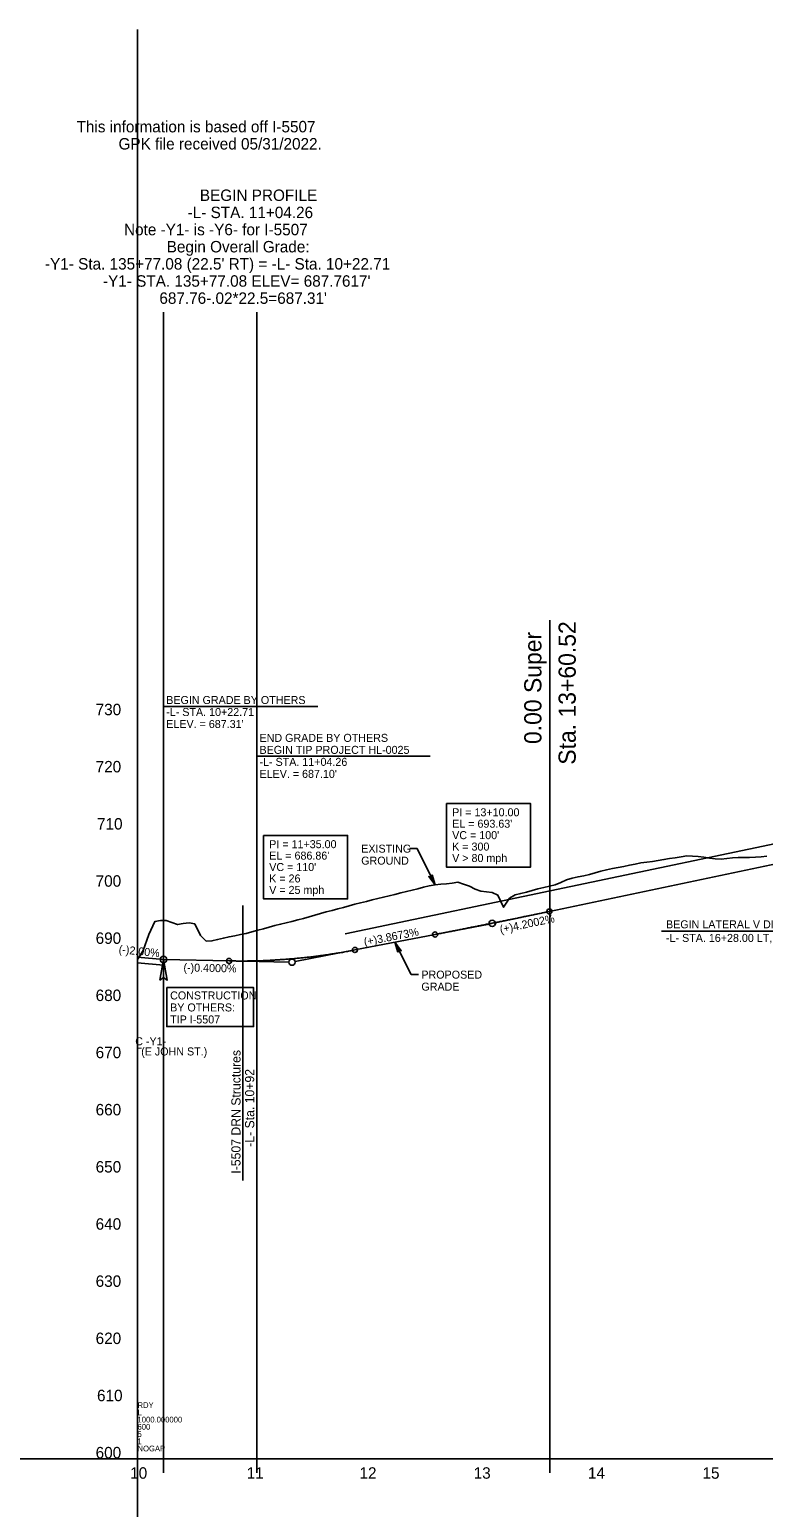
# Model space of a CAD drawing. Extents: x 1518255 to 1527303, y 471773 to 504546.
# Drawn here: x 1519476 to 1520117, y 501102 to 502395 of the extents above; entities that cross this region are included whole.
import ezdxf

# ---------------------------------------------------------------- set-up
doc = ezdxf.new("R2010")
doc.units = 0
for name, color, linetype in [('Default', 7, 'Continuous'), ('Exist Profile Cell', 7, 'Continuous'), ('Exist Vertical Profile Ground Line', 7, 'Continuous'), ('Exist Vertical Profile Horizontal Axis Label Major', 7, 'Continuous'), ('Exist Vertical Profile Vertical Axis Label', 7, 'Continuous'), ('Prop Dimension', 7, 'Continuous'), ('Prop Grid Mask', 7, 'Continuous'), ('Prop PFL Ditch Label CELL', 7, 'Continuous'), ('Prop Shade Light', 7, 'Continuous'), ('Prop Terminator CELL', 7, 'Continuous'), ('Prop Vertical Profile Curve Label', 7, 'Continuous'), ('Prop Vertical Profile Grade', 7, 'Continuous'), ('Prop Vertical Profile Grade Label', 7, 'Continuous'), ('Prop VPI Label', 7, 'Continuous'), ('Scratch_Level_1', 7, 'Continuous'), ('Scratch_Level_5', 7, 'Continuous'), ('Scratch_Level_7', 7, 'Continuous'), ('Scratch_Level_9', 7, 'Continuous')]:
    doc.layers.add(name, color=color, linetype=linetype)

msp = doc.modelspace()

# ---------------------------------------------------------------- linework, layer by layer
at = {"layer": 'Default'}
msp.add_line((1518570.4, 501145), (1519570.4, 501145), dxfattribs=at)
at = {"layer": 'Exist Profile Cell'}
for q in [(1519570.4, 502395), (1521170.4, 501145), (1519570.4, 499895)]:
    msp.add_line((1519570.4, 501145), q, dxfattribs=at)
at = {"layer": 'Exist Vertical Profile Ground Line'}
for points in [[(1519570.4, 501581.5), (1519575.4, 501589.5), (1519580.4, 501603.4), (1519585.4, 501614.8), (1519590.4, 501615.7), (1519595.4, 501615.8), (1519600.4, 501614), (1519605.4, 501612.2), (1519610.4, 501613.2), (1519615.4, 501613.8), (1519620.4, 501612.8), (1519625.4, 501602.5), (1519630.4, 501597.6), (1519635.4, 501597.9), (1519640.4, 501599), (1519645.4, 501600.4), (1519650.4, 501601.5), (1519655.4, 501602.4), (1519660.4, 501603.5), (1519665.4, 501604.5), (1519670.4, 501605.8), (1519675.4, 501607.2), (1519680.4, 501608.6), (1519685.4, 501610), (1519690.4, 501611.3), (1519695.4, 501612.5), (1519700.4, 501613.8), (1519705.4, 501615), (1519710.4, 501616.3), (1519715.4, 501617.6), (1519720.4, 501619), (1519725.4, 501620.5), (1519730.4, 501621.9), (1519735.4, 501623.2), (1519740.4, 501624.5), (1519745.4, 501625.9), (1519750.4, 501627.2), (1519755.4, 501628.6), (1519760.4, 501629.9), (1519765.4, 501631.2), (1519770.4, 501632.5), (1519775.4, 501633.7), (1519780.4, 501634.9), (1519785.4, 501636.2), (1519790.4, 501637.4), (1519795.4, 501638.6), (1519800.4, 501639.9), (1519805.4, 501641.1), (1519810.4, 501642.3), (1519815.4, 501643.5), (1519820.4, 501644.8), (1519825.4, 501646), (1519830.4, 501646.8), (1519835.4, 501647.4), (1519840.4, 501647.9), (1519845.4, 501648.5), (1519850.4, 501649.3), (1519855.4, 501647.5), (1519860.4, 501645.9), (1519865.4, 501643.1), (1519870.4, 501641.3), (1519875.4, 501640.7), (1519880.4, 501640.1), (1519885.4, 501638), (1519890.4, 501627.3), (1519895.4, 501635.2), (1519900.4, 501638.1), (1519905.4, 501639.4), (1519910.4, 501640.6), (1519915.4, 501642), (1519920.4, 501643.3), (1519925.4, 501644.6), (1519930.4, 501645.9), (1519935.4, 501647), (1519940.4, 501649.1), (1519945.4, 501651.4), (1519950.4, 501652.9), (1519955.4, 501654), (1519960.4, 501654.7), (1519965.4, 501656.1), (1519970.4, 501657.4), (1519975.4, 501658.8), (1519980.4, 501660.1), (1519985.4, 501661.1), (1519990.4, 501662.1), (1519995.4, 501663.1), (1520000.4, 501664.1), (1520005.4, 501665.1), (1520010.4, 501666.1), (1520015.4, 501666.7), (1520020.4, 501667.4), (1520025.4, 501668.2), (1520030.4, 501669), (1520035.4, 501669.9), (1520040.4, 501670.7), (1520045.4, 501671.5), (1520050.4, 501672.2), (1520055.4, 501672.1), (1520060.4, 501671.7), (1520065.4, 501671.2), (1520070.4, 501670.4)], [(1520070.4, 501670.4), (1520075.4, 501669.8), (1520080.4, 501669.4), (1520085.4, 501670), (1520090.4, 501670.7), (1520095.4, 501670.9), (1520100.4, 501670.9), (1520105.4, 501670.9), (1520110.4, 501671), (1520115.4, 501671.3), (1520120.4, 501672)]]:
    msp.add_lwpolyline(points, dxfattribs=at)
at = {"layer": 'Prop Dimension'}
for p, q in [((1519808.3, 501678.6), (1519814.7, 501678.6)), ((1519814.7, 501678.6), (1519830.4, 501646.8)), ((1519809.5, 501568.4), (1519795.4, 501596.7)), ((1519815.9, 501568.4), (1519809.5, 501568.4))]:
    msp.add_line(p, q, dxfattribs=at)
at = {"layer": 'Prop Grid Mask'}
for points in [[(1519840.4, 501718), (1519913.9, 501718), (1519913.9, 501662.5), (1519840.4, 501662.5)], [(1519680.5, 501690.2), (1519754, 501690.2), (1519754, 501634.6), (1519680.5, 501634.6)], [(1519595.9, 501557.1), (1519671.9, 501557.1), (1519671.9, 501523), (1519595.9, 501523)]]:
    msp.add_lwpolyline(points, close=True, dxfattribs=at)
at = {"layer": 'Prop PFL Ditch Label CELL'}
msp.add_line((1520028.3, 501606.5), (1520198.4, 501606.5), dxfattribs=at)
at = {"layer": 'Prop Shade Light'}
msp.add_lwpolyline([(1519570.4, 501583.8), (1519593.1, 501581.6), (1519593.1, 501576.6), (1519570.4, 501578.8)], close=True, dxfattribs=at)
at = {"layer": 'Prop Terminator CELL'}
for points in [[(1519827.8, 501655.6), (1519830.4, 501646.8), (1519825, 501654.2), (1519826.9, 501653.9)], [(1519798, 501588), (1519795.4, 501596.7), (1519800.9, 501589.3), (1519798.9, 501589.6)]]:
    msp.add_lwpolyline(points, close=True, dxfattribs=at)
at = {"layer": 'Prop Vertical Profile Curve Label'}
for p, q in [((1519593.1, 501581.6), (1519593.1, 501803)), ((1519593.1, 501803), (1519728.1, 501803)), ((1519674.7, 501580.5), (1519674.7, 501759.4)), ((1519674.7, 501759.4), (1519826.2, 501759.4)), ((1519593.1, 501581.6), (1519570.4, 501583.8)), ((1519570.4, 501583.8), (1519570.4, 501578.8)), ((1519593.1, 501576.6), (1519570.4, 501578.8)), ((1519570.4, 501578.8), (1519570.4, 501516.8)), ((1519593.1, 501576.6), (1519593.1, 501581.6))]:
    msp.add_line(p, q, dxfattribs=at)
for centre in [(1519930.4, 501623.7), (1519830.4, 501603.5), (1519760.4, 501590), (1519650.4, 501580.4)]:
    msp.add_circle(centre, 2.25, dxfattribs=at)
at = {"layer": 'Prop Vertical Profile Grade'}
for p, q in [((1519930.4, 501623.7), (1520335.4, 501708.7)), ((1519760.4, 501590), (1519830.4, 501603.5)), ((1519593.1, 501581.6), (1519650.4, 501580.4))]:
    msp.add_line(p, q, dxfattribs=at)
for points in [[(1519830.4, 501603.5), (1519832.4, 501603.9), (1519834.4, 501604.3), (1519836.4, 501604.7), (1519838.4, 501605), (1519840.4, 501605.4), (1519842.4, 501605.8), (1519844.4, 501606.2), (1519846.4, 501606.6), (1519848.4, 501607), (1519850.4, 501607.4), (1519852.4, 501607.8), (1519854.4, 501608.2), (1519856.4, 501608.6), (1519858.4, 501609), (1519860.4, 501609.4), (1519862.4, 501609.8), (1519864.4, 501610.2), (1519866.4, 501610.6), (1519868.4, 501611), (1519870.4, 501611.4), (1519872.4, 501611.8), (1519874.4, 501612.2), (1519876.4, 501612.6), (1519878.4, 501613), (1519880.4, 501613.4), (1519882.4, 501613.8), (1519884.4, 501614.2), (1519886.4, 501614.6), (1519888.4, 501615), (1519890.4, 501615.4), (1519892.4, 501615.8), (1519894.4, 501616.2), (1519896.4, 501616.6), (1519898.4, 501617), (1519900.4, 501617.4), (1519902.4, 501617.8), (1519904.4, 501618.3), (1519906.4, 501618.7), (1519908.4, 501619.1), (1519910.4, 501619.5), (1519912.4, 501619.9), (1519914.4, 501620.3), (1519916.4, 501620.7), (1519918.4, 501621.2), (1519920.4, 501621.6), (1519922.4, 501622), (1519924.4, 501622.4), (1519926.4, 501622.8), (1519928.4, 501623.2), (1519930.4, 501623.7)], [(1519674.7, 501580.5), (1519676.8, 501580.6), (1519679, 501580.6), (1519681.2, 501580.7), (1519683.4, 501580.8), (1519685.6, 501580.9), (1519687.8, 501581), (1519690, 501581.1), (1519692.2, 501581.3), (1519694.4, 501581.4), (1519696.6, 501581.6), (1519698.8, 501581.7), (1519701, 501581.9), (1519703.2, 501582.1), (1519705.4, 501582.3), (1519707.6, 501582.4), (1519709.8, 501582.7), (1519712, 501582.9), (1519714.2, 501583.1), (1519716.4, 501583.3), (1519718.6, 501583.6), (1519720.8, 501583.8), (1519723, 501584.1), (1519725.2, 501584.3), (1519727.4, 501584.6), (1519729.6, 501584.9), (1519731.8, 501585.2), (1519734, 501585.5), (1519736.2, 501585.8), (1519738.4, 501586.2), (1519740.6, 501586.5), (1519742.8, 501586.9), (1519745, 501587.2), (1519747.2, 501587.6), (1519749.4, 501587.9), (1519751.6, 501588.3), (1519753.8, 501588.7), (1519756, 501589.1), (1519758.2, 501589.5), (1519760.4, 501590)], [(1519650.4, 501580.4), (1519652.6, 501580.4), (1519654.8, 501580.4), (1519657, 501580.3), (1519659.2, 501580.3), (1519661.4, 501580.3), (1519663.6, 501580.3), (1519665.8, 501580.3), (1519668, 501580.4), (1519670.2, 501580.4), (1519672.4, 501580.4), (1519674.6, 501580.5), (1519674.7, 501580.5)]]:
    msp.add_spline(points, degree=3, dxfattribs=at)
at = {"layer": 'Prop VPI Label'}
for p, q in [((1519930.4, 501623.7), (1519883.1, 501613.7)), ((1519830.4, 501603.5), (1519877.7, 501612.6)), ((1519760.4, 501590), (1519708.1, 501579.8)), ((1519650.4, 501580.4), (1519702.7, 501579.4))]:
    msp.add_line(p, q, dxfattribs=at)
for centre in [(1519880.4, 501613.2), (1519593.1, 501581.6), (1519705.4, 501579.3)]:
    msp.add_circle(centre, 2.75, dxfattribs=at)
at = {"layer": 'Scratch_Level_1'}
for p, q in [((1519593.1, 501132.5), (1519593.1, 502147.8)), ((1519674.7, 501132.5), (1519674.7, 502147.8))]:
    msp.add_line(p, q, dxfattribs=at)
msp.add_lwpolyline([(1519590, 501563.6), (1519593.1, 501581.6), (1519596.3, 501563.5), (1519593.1, 501565.8)], close=True, dxfattribs=at)
at = {"layer": 'Scratch_Level_5'}
msp.add_line((1519662.4, 501388.4), (1519662.4, 501628.9), dxfattribs=at)
at = {"layer": 'Scratch_Level_7'}
msp.add_line((1519751.8, 501604), (1520331.8, 501725.8), dxfattribs=at)
at = {"layer": 'Scratch_Level_9'}
msp.add_line((1519930.9, 501132.5), (1519930.9, 501878.5), dxfattribs=at)

# ---------------------------------------------------------------- texts
at = {"layer": 'Exist Profile Cell'}
for s, p in [('RDY', (1519570.4, 501189.4)), ('L', (1519570.4, 501183)), ('600', (1519570.4, 501170.4)), ('1000.000000', (1519570.4, 501176.7)), ('5', (1519570.4, 501164)), ('1', (1519570.4, 501157.7)), ('NOGAP', (1519570.4, 501151.4))]:
    msp.add_text(s, height=5, dxfattribs=at).set_placement(p)
at = {"layer": 'Exist Vertical Profile Horizontal Axis Label Major'}
for s, p in [('10', (1519564, 501127.5)), ('11', (1519665.8, 501127.5)), ('12', (1519764.4, 501127.5)), ('13', (1519864.2, 501127.5)), ('14', (1519964.1, 501127.5)), ('15', (1520064.2, 501127.5))]:
    msp.add_text(s, height=10, dxfattribs=at).set_placement(p)
at = {"layer": 'Exist Vertical Profile Vertical Axis Label'}
for s, p in [('730', (1519533.8, 501795.3)), ('720', (1519533.8, 501745.3)), ('710', (1519535, 501695.3)), ('700', (1519533.8, 501645.3)), ('690', (1519533.8, 501595.3)), ('680', (1519533.8, 501545.3)), ('670', (1519533.8, 501495.3)), ('660', (1519533.8, 501445.3)), ('650', (1519533.8, 501395.3)), ('640', (1519533.8, 501345.3)), ('630', (1519533.8, 501295.3)), ('620', (1519533.8, 501245.3)), ('610', (1519535, 501195.3)), ('600', (1519533.8, 501145.3))]:
    msp.add_text(s, height=10, dxfattribs=at).set_placement(p)
at = {"layer": 'Prop Dimension'}
for s, p in [('EXISTING', (1519765.9, 501675.1)), ('GROUND', (1519765.9, 501664.6)), ('PROPOSED', (1519818.5, 501564.9)), ('GRADE', (1519818.5, 501554.4))]:
    msp.add_text(s, height=7, dxfattribs=at).set_placement(p)
at = {"layer": 'Prop PFL Ditch Label CELL'}
for s, p in [('BEGIN LATERAL V DITCH LT', (1520032.3, 501608.9)), ("-L- STA. 16+28.00 LT, ELEV. 703.90'", (1520032.3, 501597))]:
    msp.add_text(s, height=7, dxfattribs=at).set_placement(p)
at = {"layer": 'Prop Vertical Profile Curve Label'}
for s, p in [('BEGIN GRADE BY OTHERS', (1519595.5, 501805.1)), ('-L- STA. 10+22.71', (1519595.5, 501794.6)), ("ELEV. = 687.31'", (1519595.5, 501784.1)), ('END GRADE BY OTHERS', (1519677, 501772)), ('BEGIN TIP PROJECT HL-0025', (1519677, 501761.5)), ('-L- STA. 11+04.26', (1519677, 501751)), ("ELEV. = 687.10'", (1519677, 501740.5)), ("VC = 100'", (1519845.4, 501686.9)), ('K = 300', (1519845.4, 501676.9)), ("VC = 110'", (1519685.5, 501659)), ('V > 80 mph', (1519845.4, 501666.9)), ('K = 26', (1519685.5, 501649)), ('V = 25 mph', (1519685.5, 501639)), ('C -Y1-', (1519568.4, 501506.6)), ('L', (1519569.1, 501503.7)), ('  (E JOHN ST.)', (1519568.4, 501497.7))]:
    msp.add_text(s, height=7, dxfattribs=at).set_placement(p)
at = {"layer": 'Prop Vertical Profile Grade Label'}
for s, rotation, p in [('(+)4.2002%', 11.8603, (1519887.8, 501604.4)), ('(+)3.8673%', 10.944, (1519768.9, 501593.5)), ('(-)2.00%', 354.2894, (1519553.7, 501587.2)), ('(-)0.4000%', 358.8542, (1519610.5, 501571.2))]:
    msp.add_text(s, height=7, rotation=rotation, dxfattribs=at).set_placement(p)
at = {"layer": 'Prop VPI Label'}
for s, p in [('PI = 13+10.00', (1519845.4, 501706.9)), ("EL = 693.63'", (1519845.4, 501696.9)), ('PI = 11+35.00', (1519685.5, 501679)), ("EL = 686.86'", (1519685.5, 501669)), ('CONSTRUCTION', (1519598.9, 501546.7)), ('TIP I-5507', (1519598.9, 501525.7)), ('BY OTHERS:', (1519598.9, 501536.2))]:
    msp.add_text(s, height=7, dxfattribs=at).set_placement(p)
at = {"layer": 'Scratch_Level_1'}
for s, p in [('This information is based off I-5507 ', (1519517.1, 502305.1)), ('GPK file received 05/31/2022.', (1519553.8, 502290.1)), ('BEGIN PROFILE', (1519624.9, 502245.1)), ('-L- STA. 11+04.26', (1519614.2, 502230.1)), ('Note -Y1- is -Y6- for I-5507', (1519558.6, 502215.1)), ('Begin Overall Grade:', (1519595.9, 502200.1)), ("-Y1- Sta. 135+77.08 (22.5' RT) = -L- Sta. 10+22.71", (1519489.5, 502185.1)), ("-Y1- STA. 135+77.08 ELEV= 687.7617'", (1519540.2, 502170.1)), ("687.76-.02*22.5=687.31'", (1519589.5, 502155.1))]:
    msp.add_text(s, height=10, dxfattribs=at).set_placement(p)
at = {"layer": 'Scratch_Level_5'}
for s, p in [('I-5507 DRN Structures', (1519660.4, 501394.3)), ('-L- Sta. 10+92', (1519672.4, 501417.8))]:
    msp.add_text(s, height=8, rotation=90, dxfattribs=at).set_placement(p)
at = {"layer": 'Scratch_Level_9'}
for s, p in [('Sta. 13+60.52', (1519953.4, 501752)), ('0.00 Super', (1519923.4, 501770.1))]:
    msp.add_text(s, height=15, rotation=90, dxfattribs=at).set_placement(p)

doc.saveas('drawing.dxf')
